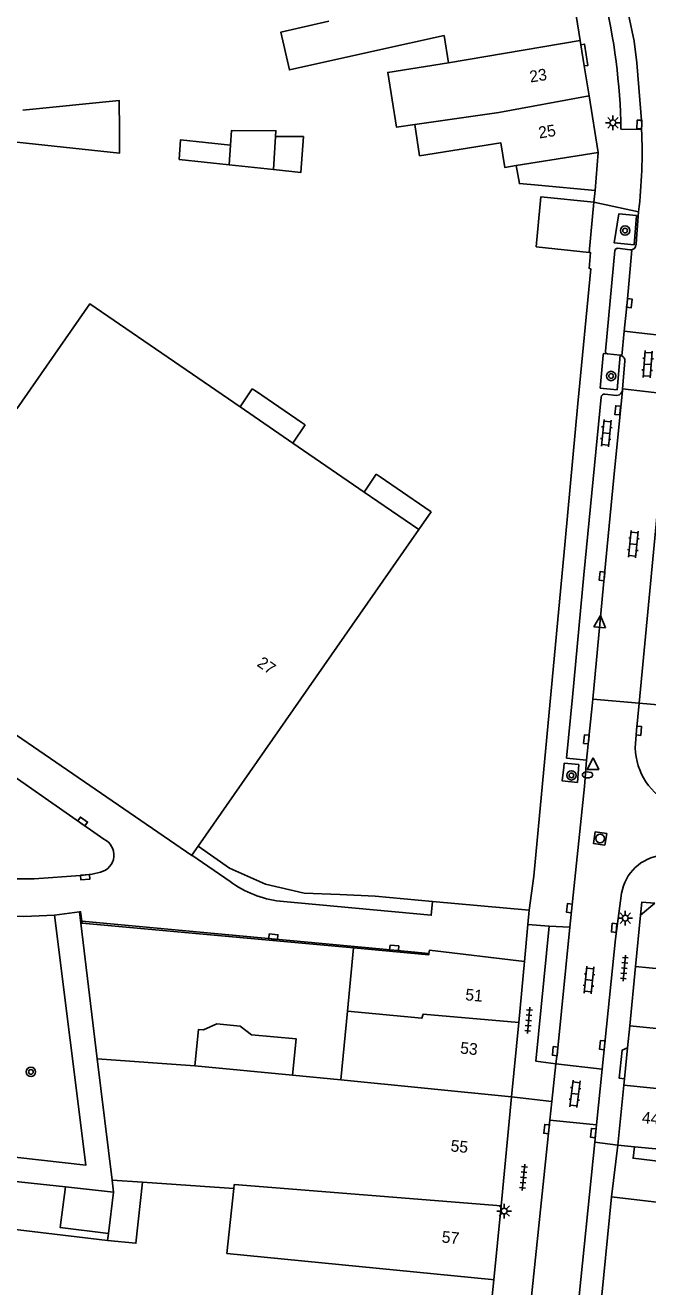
# Model space of a CAD drawing. Extents: x 132998 to 136004, y 396998 to 398512.
# Drawn here: x 133683.8 to 133737.1, y 397305.5 to 397413.5 of the extents above; entities that cross this region are included whole.
import ezdxf

# ---------------------------------------------------------------- set-up
doc = ezdxf.new("R2010")
doc.units = 0
for name, color, linetype in [('gg-afsc-erfafscheiding', 7, 'Continuous'), ('gg-afsc-hekwerk', 7, 'Continuous'), ('gg-afsc-muur', 7, 'Continuous'), ('gg-anno-huisnummerreeks BGT', 7, 'Continuous'), ('gg-bbg-bijgebouw', 7, 'Continuous'), ('gg-bbg-bordes', 7, 'Continuous'), ('gg-bbg-gedigitaliseerde bebouwing', 7, 'Continuous'), ('gg-bbg-gedigitaliseerde bijgebouw', 7, 'Continuous'), ('gg-bbg-hoofdgebouw', 7, 'Continuous'), ('gg-bbg-luifel en loopbrug', 7, 'Continuous'), ('gg-bbg-onder overbouw', 7, 'Continuous'), ('gg-bbg-pand overbouw', 7, 'Continuous'), ('gg-bbg-tussenscheiding', 7, 'Continuous'), ('gg-knt-verharding', 7, 'Continuous'), ('gg-knt-verharding nz', 7, 'Continuous'), ('gt-grn-weggrens', 7, 'Continuous'), ('gt-symb-boom', 7, 'Continuous'), ('gt-symb-brandkraan', 7, 'Continuous'), ('gt-symb-klinker verharding', 7, 'Continuous'), ('gt-symb-kolk', 7, 'Continuous'), ('gt-symb-lichtmast', 7, 'Continuous'), ('gt-symb-rioolschacht', 7, 'Continuous'), ('gt-symb-tegel verharding', 7, 'Continuous'), ('gt-symb-waterafsluiter', 7, 'Continuous')]:
    doc.layers.add(name, color=color, linetype=linetype)

# ---------------------------------------------------------------- blocks, each defined once
blk = doc.blocks.new('gt0-KOLK')
at = {"layer": 'gt-symb-kolk'}
blk.add_lwpolyline([(0, 0), (0.38, 0), (0.38, 0.4), (-0.37, 0.4), (-0.37, 0), (0, 0)], dxfattribs=at)
blk = doc.blocks.new('gt0-BOOM')
at = {"layer": 'gt-symb-boom'}
for radius in [0.4, 0.2]:
    blk.add_circle((0, 0), radius, dxfattribs=at)
blk = doc.blocks.new('gt0-KL1')
at = {"layer": 'gt-symb-klinker verharding'}
for p, q in [((-1.15, 0.3), (1.15, 0.3)), ((-1, -0.3), (-1, 0.3)), ((-0.5, 0.3), (-0.5, 0.45)), ((0, -0.3), (0, 0.3)), ((0.5, 0.3), (0.5, 0.45)), ((1, -0.3), (1, 0.3)), ((-1.15, -0.3), (1.15, -0.3)), ((-0.5, -0.45), (-0.5, -0.3)), ((0.5, -0.45), (0.5, -0.3))]:
    blk.add_line(p, q, dxfattribs=at)
blk = doc.blocks.new('gt0-LMAST')
at = {"layer": 'gt-symb-lichtmast'}
for p, q in [((-0.18, 0.17), (-0.45, 0.44)), ((-0.01, 0.25), (-0.01, 0.62)), ((0.17, 0.17), (0.44, 0.44)), ((-0.26, 0), (-0.63, 0)), ((-0.18, -0.18), (-0.45, -0.45)), ((-0.01, -0.25), (-0.01, -0.63)), ((0.44, -0.45), (0.17, -0.18)), ((0.24, 0), (0.62, 0))]:
    blk.add_line(p, q, dxfattribs=at)
blk.add_circle((-0.01, 0), 0.25, dxfattribs=at)
blk = doc.blocks.new('gt0-WAFSL')
at = {"layer": 'gt-symb-waterafsluiter'}
for p, q in [((-0.5, -0.33), (0, 0.67)), ((0, 0.67), (0.5, -0.33)), ((0.5, -0.33), (-0.5, -0.33))]:
    blk.add_line(p, q, dxfattribs=at)
blk = doc.blocks.new('gt0-RS')
at = {"layer": 'gt-symb-rioolschacht'}
blk.add_lwpolyline([(-0.5, -0.5), (0.5, -0.5), (0.5, 0.5), (-0.5, 0.5)], close=True, dxfattribs=at)
blk.add_circle((0, 0), 0.375, dxfattribs=at)
blk = doc.blocks.new('gt0-BR')
at = {"layer": 'gt-symb-brandkraan'}
for centre, radius, start, end in [((-0.24, 0), 0.206, 107.5669, 252.4331), ((0.6, -2.66), 3, 106.892, 107.5669), ((0, -0.69), 0.938, 73.108, 106.892), ((-0.6, -2.66), 3, 72.4331, 73.108), ((0.24, 0), 0.206, 287.567, 72.4331), ((0.6, 2.66), 3, 252.4331, 253.108), ((0, 0.69), 0.938, 253.108, 286.8921), ((-0.6, 2.66), 3, 286.8921, 287.567)]:
    blk.add_arc(centre, radius, start, end, dxfattribs=at)
blk = doc.blocks.new('gt0-TEG1')
at = {"layer": 'gt-symb-tegel verharding'}
for p, q in [((-1.12, 0), (1.13, 0)), ((-0.9, -0.25), (-0.9, 0.25)), ((-0.45, -0.25), (-0.45, 0.25)), ((0, -0.25), (0, 0.25)), ((0.45, -0.25), (0.45, 0.25)), ((0.9, -0.25), (0.9, 0.25))]:
    blk.add_line(p, q, dxfattribs=at)

msp = doc.modelspace()

# ---------------------------------------------------------------- linework, layer by layer
at = {"layer": 'gg-afsc-erfafscheiding'}
for p, q in [((133732.6, 397399.34), (133732.48, 397398.34)), ((133723.92, 397306.1), (133723.4, 397301.12))]:
    msp.add_line(p, q, dxfattribs=at)
msp.add_lwpolyline([(133756.13, 397314.05), (133735.85, 397316.5), (133735.97, 397317.49)], dxfattribs=at)
at = {"layer": 'gg-afsc-hekwerk'}
for p, q in [((133726.94, 397337.74), (133718.68, 397338.48)), ((133726.83, 397336.51), (133726.94, 397337.74)), ((133726.56, 397333.34), (133726.83, 397336.51))]:
    msp.add_line(p, q, dxfattribs=at)
for points in [[(133726.94, 397337.74), (133727.34, 397340.64), (133730.03, 397369.33), (133731.11, 397381.12), (133732.23, 397392.65), (133732.1, 397392.66), (133732.21, 397394.04), (133732.09, 397394.05)], [(133718.68, 397338.48), (133713.76, 397338.93), (133710.74, 397339.08), (133707.67, 397339.2), (133704.36, 397339.97), (133701.3, 397341.33), (133698.6, 397343.21)], [(133686.31, 397337.32), (133688.99, 397315.91), (133665.14, 397318.6), (133652.44, 397319.77)], [(133686.31, 397337.32), (133683.69, 397337.2), (133680.64, 397337.25), (133677.66, 397337.4)]]:
    msp.add_lwpolyline(points, dxfattribs=at)
at = {"layer": 'gg-afsc-muur'}
for p, q in [((133703.24, 397382.37), (133703.59, 397382.13)), ((133707.43, 397379.52), (133707.78, 397379.28)), ((133713.85, 397375.07), (133714.2, 397374.84)), ((133718.02, 397372.21), (133718.55, 397371.84)), ((133688.55, 397336.62), (133688.43, 397337.59)), ((133688.66, 397336.63), (133688.55, 397336.62)), ((133689.97, 397325), (133688.55, 397336.62)), ((133688.66, 397336.63), (133688.64, 397336.8)), ((133711.9, 397334.52), (133688.66, 397336.63))]:
    msp.add_line(p, q, dxfattribs=at)
msp.add_lwpolyline([(133688.43, 397337.59), (133688.54, 397337.61), (133688.64, 397336.8)], dxfattribs=at)
at = {"layer": 'gg-bbg-bijgebouw'}
for p, q in [((133732.85, 397402.6), (133732.6, 397399.34)), ((133732.6, 397399.34), (133727.71, 397399.8)), ((133691.36, 397313.61), (133687.24, 397314.05))]:
    msp.add_line(p, q, dxfattribs=at)
at = {"layer": 'gg-bbg-bordes'}
for p, q in [((133703.24, 397382.37), (133702.2, 397380.82)), ((133703.59, 397382.13), (133707.43, 397379.52)), ((133707.78, 397379.28), (133706.71, 397377.72)), ((133713.85, 397375.07), (133712.81, 397373.53)), ((133714.2, 397374.84), (133718.02, 397372.21)), ((133717.49, 397370.32), (133718.55, 397371.84))]:
    msp.add_line(p, q, dxfattribs=at)
at = {"layer": 'gg-bbg-gedigitaliseerde bebouwing'}
for p, q in [((133691.24, 397314.63), (133689.97, 397325)), ((133689.97, 397325), (133698.33, 397324.42)), ((133706.69, 397323.6), (133710.82, 397323.2)), ((133735.97, 397317.49), (133734.55, 397317.63)), ((133701.67, 397313.9), (133693.83, 397314.45))]:
    msp.add_line(p, q, dxfattribs=at)
for points in [[(133709.79, 397413.84), (133705.69, 397412.91), (133706.42, 397409.67), (133714, 397411.37)], [(133720.04, 397410.28), (133719.67, 397412.62), (133714, 397411.37)], [(133717.15, 397405), (133715.59, 397404.76), (133714.84, 397409.46), (133720.04, 397410.28)], [(133725.85, 397401.48), (133724.86, 397401.33), (133724.52, 397403.44), (133717.57, 397402.33), (133717.15, 397405)], [(133743.22, 397321.94), (133750.31, 397321.24), (133750, 397318.13), (133742.8, 397318.84), (133742.61, 397316.84), (133735.97, 397317.49)], [(133701.67, 397313.9), (133701.07, 397308.35), (133723.73, 397306.12)]]:
    msp.add_lwpolyline(points, dxfattribs=at)
at = {"layer": 'gg-bbg-gedigitaliseerde bijgebouw'}
for p, q in [((133705.24, 397403.97), (133705.05, 397401.15)), ((133701.26, 397401.56), (133701.37, 397403.23)), ((133701.26, 397401.56), (133705.05, 397401.15)), ((133691.36, 397313.61), (133691.24, 397314.63)), ((133690.92, 397310.06), (133690.84, 397309.46))]:
    msp.add_line(p, q, dxfattribs=at)
for points in [[(133683.58, 397406.24), (133691.84, 397407.07), (133691.86, 397404.51)], [(133691.86, 397404.51), (133691.87, 397402.55), (133679.05, 397403.91)], [(133701.37, 397403.23), (133701.45, 397404.48), (133705.27, 397404.47), (133705.24, 397403.97)], [(133727.71, 397399.8), (133726.12, 397399.95), (133725.85, 397401.48)], [(133698.33, 397324.42), (133698.63, 397327.52), (133699.07, 397327.48), (133700.19, 397328.01), (133702.2, 397327.81), (133703.18, 397327.08), (133707, 397326.71), (133706.69, 397323.6)], [(133687.24, 397314.05), (133686.8, 397310.57), (133690.92, 397310.06)], [(133690.84, 397309.46), (133693.27, 397309.22), (133693.83, 397314.45)]]:
    msp.add_lwpolyline(points, dxfattribs=at)
at = {"layer": 'gg-bbg-hoofdgebouw'}
for p, q in [((133731.33, 397412.18), (133730.72, 397415.98)), ((133731.38, 397411.83), (133731.33, 397412.18)), ((133731.67, 397410.01), (133731.38, 397411.83)), ((133732.08, 397407.45), (133731.67, 397410.01)), ((133732.85, 397402.6), (133732.08, 397407.45)), ((133732.48, 397398.34), (133732.09, 397394.05)), ((133706.71, 397377.72), (133702.2, 397380.82)), ((133712.81, 397373.53), (133706.71, 397377.72)), ((133717.49, 397370.32), (133712.81, 397373.53)), ((133698.6, 397343.21), (133717.49, 397370.32)), ((133698.07, 397342.46), (133698.6, 397343.21)), ((133736.06, 397332.93), (133736.49, 397337.3)), ((133711.9, 397334.52), (133711.38, 397329.1)), ((133726.56, 397333.34), (133726.07, 397328.13)), ((133735.56, 397327.84), (133736.06, 397332.93)), ((133711.38, 397329.1), (133710.82, 397323.2)), ((133726.07, 397328.13), (133725.45, 397321.77)), ((133735.37, 397325.94), (133735.56, 397327.84)), ((133735.11, 397323.3), (133735.37, 397325.94)), ((133734.55, 397317.63), (133735.05, 397322.75)), ((133735.05, 397322.75), (133735.11, 397323.3)), ((133725.45, 397321.77), (133724.54, 397312.44)), ((133734.01, 397313.21), (133732.75, 397300.44)), ((133734.01, 397313.21), (133796.8, 397305.74)), ((133724.54, 397312.44), (133723.92, 397306.1)), ((133723.92, 397306.1), (133723.73, 397306.12))]:
    msp.add_line(p, q, dxfattribs=at)
for points in [[(133732.48, 397398.34), (133727.95, 397398.82), (133727.56, 397394.53), (133732.09, 397394.05)], [(133702.2, 397380.82), (133689.33, 397389.66), (133683.09, 397380.67)], [(133670.11, 397361.99), (133669.91, 397361.71), (133698.06, 397342.43), (133698.07, 397342.46)], [(133718.37, 397334.04), (133718.35, 397333.91), (133711.9, 397334.52)], [(133726.56, 397333.34), (133718.41, 397334.3), (133718.37, 397334.04)]]:
    msp.add_lwpolyline(points, dxfattribs=at)
at = {"layer": 'gg-bbg-luifel en loopbrug'}
msp.add_line((133687.24, 397314.05), (133678.79, 397314.95), dxfattribs=at)
for points in [[(133701.37, 397403.23), (133697.09, 397403.68), (133696.98, 397402.01), (133701.26, 397401.56)], [(133705.05, 397401.15), (133707.41, 397400.9), (133707.62, 397403.97), (133705.24, 397403.97)], [(133690.84, 397309.46), (133680.53, 397310.68), (133680.02, 397306.31), (133676.32, 397306.75)]]:
    msp.add_lwpolyline(points, dxfattribs=at)
at = {"layer": 'gg-bbg-onder overbouw'}
msp.add_line((133736.49, 397337.3), (133737.71, 397338.33), dxfattribs=at)
at = {"layer": 'gg-bbg-pand overbouw'}
msp.add_lwpolyline([(133736.49, 397337.3), (133736.6, 397338.43), (133737.71, 397338.33)], dxfattribs=at)
at = {"layer": 'gg-bbg-tussenscheiding'}
for p, q in [((133731.33, 397412.18), (133720.04, 397410.28)), ((133732.85, 397402.6), (133725.85, 397401.48)), ((133736.06, 397332.93), (133747.63, 397331.77)), ((133735.56, 397327.84), (133750.68, 397326.33)), ((133698.33, 397324.42), (133706.69, 397323.6)), ((133710.82, 397323.2), (133725.45, 397321.77)), ((133743.22, 397321.94), (133735.05, 397322.75)), ((133693.83, 397314.45), (133691.24, 397314.63)), ((133691.36, 397313.61), (133690.92, 397310.06))]:
    msp.add_line(p, q, dxfattribs=at)
for points in [[(133732.08, 397407.45), (133724.35, 397406.04), (133717.15, 397405)], [(133726.07, 397328.13), (133717.87, 397328.83), (133717.76, 397328.48), (133711.38, 397329.1)], [(133701.67, 397313.9), (133701.7, 397314.24), (133724.54, 397312.44)]]:
    msp.add_lwpolyline(points, dxfattribs=at)
at = {"layer": 'gg-knt-verharding'}
for p, q in [((133736.57, 397404.58), (133734.8, 397404.6)), ((133736.32, 397397.53), (133736.13, 397395.2)), ((133736.13, 397395.2), (133736.1, 397394.7)), ((133733.48, 397385.6), (133734.29, 397394.21)), ((133735.09, 397387.3), (133734.89, 397385.2)), ((133739.34, 397386.83), (133735.09, 397387.3)), ((133733.04, 397382.42), (133733.3, 397385.26)), ((133733.65, 397385.37), (133734.74, 397385.24)), ((133734.48, 397382.29), (133734.74, 397385.24)), ((133734.93, 397382.36), (133735.13, 397384.75)), ((133734.48, 397382.29), (133733.04, 397382.42)), ((133738.87, 397381.92), (133734.93, 397382.36)), ((133734.93, 397382.24), (133734.93, 397382.36)), ((133738.87, 397381.92), (133736.36, 397355.46)), ((133733.12, 397381.66), (133731.64, 397366.44)), ((133731.64, 397366.44), (133730.65, 397355.98)), ((133730.65, 397355.98), (133730.15, 397350.74)), ((133730.15, 397350.74), (133731.87, 397350.57)), ((133731.87, 397350.57), (133731.68, 397348.34)), ((133731.68, 397348.34), (133730.43, 397336.29)), ((133698.07, 397342.46), (133701.34, 397340.18)), ((133734.34, 397335.28), (133734.86, 397339.19)), ((133730.43, 397336.29), (133728.66, 397336.36)), ((133734.34, 397335.28), (133733.2, 397324.14)), ((133729.23, 397324.58), (133728.89, 397321.36)), ((133729.23, 397324.58), (133733.2, 397324.14)), ((133733.2, 397324.14), (133732.71, 397319.37)), ((133728.89, 397321.36), (133728.73, 397319.75)), ((133728.73, 397319.75), (133726.63, 397299.62)), ((133732.71, 397319.37), (133728.73, 397319.75)), ((133732.71, 397319.37), (133732.56, 397317.89)), ((133732.56, 397317.89), (133730.83, 397300.68)), ((133734.01, 397313.21), (133734.55, 397317.63))]:
    msp.add_line(p, q, dxfattribs=at)
for points in [[(133731.38, 397411.83), (133731.68, 397411.88), (133731.97, 397410.05), (133731.67, 397410.01)], [(133736.14, 397397.2), (133734.62, 397397.35), (133734.23, 397394.87), (133735.93, 397394.71), (133736.14, 397397.2)], [(133734.51, 397394.4), (133735.61, 397394.28), (133735.73, 397394.28)], [(133733.3, 397385.26), (133733.32, 397385.41), (133733.65, 397385.37)], [(133734.74, 397385.24), (133734.76, 397385.24), (133734.89, 397385.2)], [(133733.43, 397381.91), (133734.44, 397381.81), (133734.68, 397381.86), (133734.78, 397381.93), (133734.87, 397382.07), (133734.93, 397382.24)], [(133690.54, 397343.83), (133679.31, 397351.64), (133668.41, 397359.24)], [(133736.05, 397352.02), (133736.14, 397353.12), (133736.36, 397355.46)], [(133729.92, 397349.99), (133729.79, 397348.8), (133731.1, 397348.68)], [(133729.92, 397349.99), (133729.95, 397350.32), (133731.2, 397350.2), (133731.1, 397348.68)], [(133662.62, 397341.61), (133681.55, 397340.43), (133684.55, 397340.43), (133688.52, 397340.71), (133689.53, 397340.83), (133690.25, 397340.99)], [(133705.61, 397338.51), (133718.57, 397337.3), (133718.68, 397338.48)], [(133688.64, 397336.8), (133715.37, 397334.31), (133718.37, 397334.04)], [(133728.66, 397336.36), (133727.53, 397324.81), (133729.23, 397324.58)], [(133735.11, 397323.3), (133734.66, 397323.35), (133734.9, 397325.74), (133735.37, 397325.94)]]:
    msp.add_lwpolyline(points, dxfattribs=at)
for centre, radius, start, end in [((133681.77, 397403.67), 53.05, 1.0057, 13.5807), ((133692.37, 397402.68), 44.25, 353.3256, 2.4629), ((133734.5, 397394.18), 0.216, 87.1839, 172.5773), ((133735.66, 397394.71), 0.436, 278.7992, 357.7793), ((133733.67, 397385.56), 0.192, 168.9734, 262.388), ((133734.71, 397384.81), 0.427, 351.6013, 64.8479), ((133733.4, 397381.64), 0.279, 82.7678, 176.0101), ((133741.49, 397351.75), 5.45, 177.145, 242.048), ((133689.87, 397342.46), 1.52, 284.6361, 64.0862), ((133738.73, 397338.54), 3.92, 96.3362, 170.472), ((133706.66, 397347.46), 9.01, 233.7871, 263.3415)]:
    msp.add_arc(centre, radius, start, end, dxfattribs=at)
at = {"layer": 'gg-knt-verharding nz'}
for p, q in [((133734.2, 397374.79), (133734.93, 397382.24)), ((133734.2, 397374.79), (133733.4, 397366.51)), ((133732.4, 397355.79), (133733.4, 397366.51)), ((133732.35, 397355.22), (133731.87, 397350.57)), ((133732.35, 397355.22), (133732.4, 397355.79)), ((133686.31, 397337.32), (133688.43, 397337.59))]:
    msp.add_line(p, q, dxfattribs=at)
for points in [[(133734.96, 397416.73), (133735.94, 397412.13), (133736.16, 397410.27), (133736.59, 397404.99), (133736.57, 397404.58)], [(133735.73, 397394.28), (133735.33, 397389.73), (133735.09, 397387.3)], [(133730.43, 397336.29), (133729.38, 397325.64), (133729.23, 397324.58)]]:
    msp.add_lwpolyline(points, dxfattribs=at)
at = {"layer": 'gt-grn-weggrens'}
for p, q in [((133736.32, 397397.53), (133732.48, 397398.34)), ((133736.36, 397355.46), (133732.4, 397355.79)), ((133736.36, 397355.46), (133738.62, 397355.26)), ((133728.66, 397336.36), (133726.83, 397336.51)), ((133728.89, 397321.36), (133725.45, 397321.77)), ((133732.56, 397317.89), (133734.55, 397317.63))]:
    msp.add_line(p, q, dxfattribs=at)

# ---------------------------------------------------------------- block references
at = {"layer": 'gt-symb-boom'}
for p in [(133735.16, 397395.92), (133733.97, 397383.47), (133730.57, 397349.28), (133684.28, 397323.89)]:
    msp.add_blockref('gt0-BOOM', p, dxfattribs=at)
at = {"layer": 'gt-symb-brandkraan'}
msp.add_blockref('gt0-BR', (133731.95, 397349.32), dxfattribs=at)
at = {"layer": 'gt-symb-klinker verharding'}
for p, rotation in [((133737.1, 397384.47), 85.41237434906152), ((133733.55, 397378.58), 84.54608111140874), ((133735.88, 397369.07), 84.37493990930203), ((133732.08, 397331.76), 84.48902304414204), ((133730.87, 397322.01), -97.06814005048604)]:
    msp.add_blockref('gt0-KL1', p, dxfattribs=dict(at, rotation=rotation))
at = {"layer": 'gt-symb-kolk'}
for p, rotation in [((133736.59, 397404.99), 88.22439947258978), ((133735.33, 397389.73), -95.52028509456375), ((133734.73, 397380.5), 84.60853660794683), ((133733.39, 397366.31), 84.7225939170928), ((133736.14, 397353.12), -95.1396297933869), ((133732.05, 397352.34), 84.22035165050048), ((133688.59, 397345.17), -34.905419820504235), ((133688.92, 397340.76), -175.72694172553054), ((133730.59, 397337.88), 84.0329623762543), ((133734.43, 397336.2), 84.20389934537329), ((133705.02, 397335.27), -5.3259449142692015), ((133715.37, 397334.31), -5.066567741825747), ((133729.38, 397325.64), 84.37493990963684), ((133733.41, 397326.16), 84.1469086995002), ((133728.64, 397318.97), 84.03296237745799), ((133732.64, 397318.63), 84.2038993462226)]:
    msp.add_blockref('gt0-KOLK', p, dxfattribs=dict(at, rotation=rotation))
at = {"layer": 'gt-symb-lichtmast'}
for p in [(133734.13, 397405.15), (133735.19, 397337.06), (133724.82, 397311.98)]:
    msp.add_blockref('gt0-LMAST', p, dxfattribs=at)
at = {"layer": 'gt-symb-rioolschacht', "rotation": 81.43241009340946}
msp.add_blockref('gt0-RS', (133733.02, 397343.87), dxfattribs=at)
at = {"layer": 'gt-symb-tegel verharding'}
for p, rotation in [((133735.1, 397332.78), -95.79610065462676), ((133726.9, 397328.3), 84.66555996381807), ((133726.47, 397314.86), 84.4890230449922)]:
    msp.add_blockref('gt0-TEG1', p, dxfattribs=dict(at, rotation=rotation))
at = {"layer": 'gt-symb-waterafsluiter', "rotation": -5.334440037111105}
msp.add_blockref('gt0-WAFSL', (133733.01, 397362.29), dxfattribs=at)
at = {"layer": 'gt-symb-waterafsluiter'}
msp.add_blockref('gt0-WAFSL', (133732.42, 397350.12), dxfattribs=at)

# ---------------------------------------------------------------- texts
at = {"layer": 'gg-anno-huisnummerreeks BGT'}
for s, rotation, p in [('23', 9, (133727.06, 397408.59)), ('25', 9, (133727.82, 397403.8)), ('27', 325.1, (133703.57, 397358.7)), ('51', 354.7, (133721.45, 397330.03)), ('53', 354.4, (133721.01, 397325.47)), ('44-44a', 354.4, (133736.57, 397319.51)), ('55', 354.4, (133720.19, 397317.09)), ('57', 354.4, (133719.43, 397309.29))]:
    msp.add_text(s, height=1, rotation=rotation, dxfattribs=at).set_placement(p)

doc.saveas('drawing.dxf')
